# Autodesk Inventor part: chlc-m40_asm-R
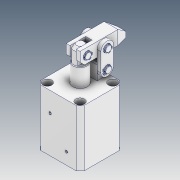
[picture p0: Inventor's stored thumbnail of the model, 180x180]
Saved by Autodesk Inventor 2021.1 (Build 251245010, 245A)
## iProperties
Created: 2019-11
Part Number: chlc-m40_asm-R
Material: Ogólny
Description: STEP AP214
Document SubType Name: Modeling
Designer: user
Density: 1 g/cm^3
Appearance: Domyślna
Company: Microsoft
Title: chlc-m40_asm-R.STEP
Author: Windows
Revision Number: ÈÎºÎ
Sending System: SolidWorks 2015
Preprocessor: SwSTEP 2.0
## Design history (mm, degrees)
feature "CHLC-40-03-2-solid1"
feature "CHLC-40-08-1-solid1"
feature "CHLC-40-͹̨-1-solid1"
feature "CHLC-40-06-3-solid1"
feature "CHLC-40-06-1-solid1"
feature "CHLC-40-03-1-solid1"
feature "CHLC-40-06-6-solid1"
feature "CHLC-40-02-2-solid1"
feature "CHLC-40-06-2-solid1"
feature "CHLC-40-01-1-solid1"
feature "CHLC-40-06-4-solid1"
feature "CHLC-40-04-1-solid1"
feature "CHLC-40-06-5-solid1"
feature "CHLC-40-02-1-solid1"
feature "NONE"
node "Bryła1"
node "Bryła2"
node "Bryła3"
node "Bryła4"
node "Bryła5"
node "Bryła6"
node "Bryła7"
node "Bryła8"
node "Bryła9"
node "Bryła10"
node "Bryła11"
node "Bryła12"
node "Bryła13"
node "Bryła14"
node "Bryła15"
